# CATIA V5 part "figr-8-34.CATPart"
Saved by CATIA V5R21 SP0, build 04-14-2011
Part number: Part1
Bounding box of the stored display mesh (mm): x -75 to 75, y -75 to 75, z 0 to 20
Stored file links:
  D:\CATIA V5R21 E-RESOURCES\CATIA-V5R21\catia-v5r21-prt\c08-catia-v5r20-prt\c08-catia-v5r21-figr-8-34.CATPart
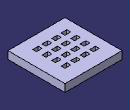
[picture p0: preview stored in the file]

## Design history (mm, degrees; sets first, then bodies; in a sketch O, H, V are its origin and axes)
Body1 (main body)
  Sketch1 on xy-plane, origin (0, 0, 0), H (1, 0, 0), V (0, 1, 0)
    line L1 (-75, 75) -> (75, 75)
    line L2 (75, 75) -> (75, -75)
    line L3 (75, -75) -> (-75, -75)
    line L4 (-75, -75) -> (-75, 75)
    axis line L5 (75, -75) -> (-75, 75)
    length L3 = 150
    length L2 = 150
    horizontal: L1 H, L3 H
    vertical: L2 V, L4 V
    midpoint: O L5
  Pad1: profile Sketch1, direction (0, 0, 1), length 20
  Sketch2 on face of Pad1, origin (0, 0, 20), H (1, 0, 0), V (0, 1, 0)
    line L1 (25, 40) -> (40, 40)
    line L2 (40, 40) -> (40, 30)
    line L3 (40, 30) -> (25, 30)
    line L4 (25, 30) -> (25, 40)
    reference projected line E1 (75, -75) -> (75, 75) from edge [face of Pad1 | face of Pad1]
    reference projected line E2 (75, 75) -> (-75, 75) from edge [face of Pad1 | face of Pad1]
    length L3 = 15
    length L4 = 10
    distance L2 E1 = 35
    distance L1 E2 = 35
    horizontal: L1 H, L3 H
    vertical: L2 V, L4 V
  Pocket1: profile Sketch2, direction (0, 0, -1), through (limit type 3)
  RectPattern1: of Pocket1, direction 1 instances 4, spacing 25, along end face of Pad1 reversed, direction 2 instances 4, spacing 25, along end face of Pad1 reversed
